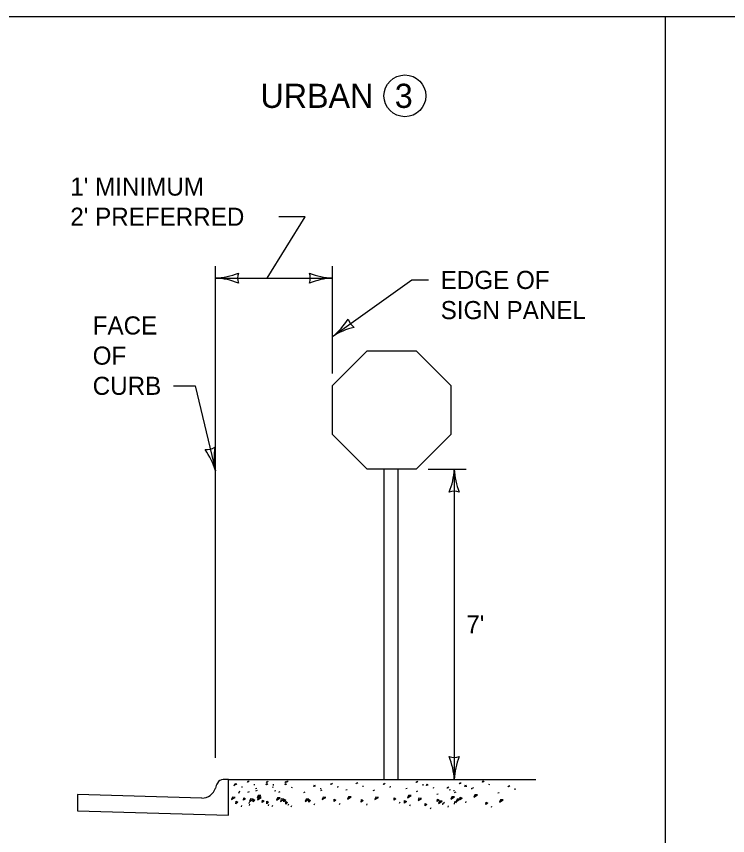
# Model space of a CAD drawing. Extents: x 49991.4 to 50021, y 49987.6 to 50011.4.
# Drawn here: x 50005.916 to 50008.274, y 49996.284 to 49998.999 of the extents above; entities that cross this region are included whole.
import ezdxf

# ---------------------------------------------------------------- set-up
doc = ezdxf.new("R2010")
doc.units = 0
for name, color, linetype in [('Level 1', 7, 'Continuous'), ('Level 2', 7, 'Continuous'), ('Level 3', 7, 'Continuous')]:
    doc.layers.add(name, color=color, linetype=linetype)

msp = doc.modelspace()

# ---------------------------------------------------------------- linework, layer by layer
at = {"layer": 'Level 1'}
for p, q in [((50007.1354, 49996.4699), (50007.1354, 49997.4987)), ((50007.1816, 49996.4699), (50007.1816, 49997.4987)), ((50006.6189, 49996.4699), (50006.6019, 49996.4699)), ((50006.6189, 49996.4699), (50007.6386, 49996.4699)), ((50006.6189, 49996.3514), (50006.6189, 49996.4699)), ((50006.6402, 49996.4554), (50006.637, 49996.4475)), ((50006.6411, 49996.4529), (50006.6431, 49996.4577)), ((50006.6456, 49996.454), (50006.6411, 49996.4529)), ((50006.6431, 49996.4577), (50006.6456, 49996.454)), ((50006.682, 49996.4609), (50006.684, 49996.4657)), ((50006.6865, 49996.462), (50006.682, 49996.4609)), ((50006.684, 49996.4657), (50006.6865, 49996.462)), ((50006.7049, 49996.4514), (50006.7054, 49996.455)), ((50006.7436, 49996.4529), (50006.7456, 49996.4577)), ((50006.7481, 49996.454), (50006.7436, 49996.4529)), ((50006.7449, 49996.46), (50006.7469, 49996.4648)), ((50006.7494, 49996.4611), (50006.7449, 49996.46)), ((50006.7456, 49996.4577), (50006.7481, 49996.454)), ((50006.7469, 49996.4648), (50006.7494, 49996.4611)), ((50006.7678, 49996.4505), (50006.7683, 49996.4541)), ((50006.8065, 49996.452), (50006.8085, 49996.4568)), ((50006.811, 49996.4531), (50006.8065, 49996.452)), ((50006.8074, 49996.46), (50006.8094, 49996.4648)), ((50006.8119, 49996.4611), (50006.8074, 49996.46)), ((50006.8085, 49996.4568), (50006.811, 49996.4531)), ((50006.8111, 49996.4609), (50006.8131, 49996.4657)), ((50006.8156, 49996.462), (50006.8111, 49996.4609)), ((50006.8131, 49996.4657), (50006.8156, 49996.462)), ((50006.9018, 49996.4473), (50006.9039, 49996.452)), ((50006.9039, 49996.452), (50006.9063, 49996.4484)), ((50006.9587, 49996.4537), (50006.9607, 49996.4585)), ((50006.9632, 49996.4548), (50006.9587, 49996.4537)), ((50006.9607, 49996.4585), (50006.9632, 49996.4548)), ((50007.0425, 49996.4553), (50007.0446, 49996.46)), ((50007.0446, 49996.46), (50007.047, 49996.4564)), ((50007.1326, 49996.4537), (50007.1347, 49996.4585)), ((50007.1371, 49996.4548), (50007.1326, 49996.4537)), ((50007.1347, 49996.4585), (50007.1371, 49996.4548)), ((50007.2416, 49996.46), (50007.2437, 49996.4648)), ((50007.2461, 49996.4611), (50007.2416, 49996.46)), ((50007.2437, 49996.4648), (50007.2461, 49996.4611)), ((50007.2646, 49996.4505), (50007.265, 49996.4541)), ((50007.276, 49996.4505), (50007.278, 49996.4552)), ((50007.2805, 49996.4515), (50007.276, 49996.4505)), ((50007.278, 49996.4552), (50007.2805, 49996.4515)), ((50007.385, 49996.4553), (50007.3871, 49996.46)), ((50007.3895, 49996.4564), (50007.385, 49996.4553)), ((50007.3871, 49996.46), (50007.3895, 49996.4564)), ((50007.4024, 49996.4473), (50007.4044, 49996.452)), ((50007.4044, 49996.452), (50007.4068, 49996.4484)), ((50007.4608, 49996.4616), (50007.4629, 49996.4663)), ((50007.4653, 49996.4627), (50007.4608, 49996.4616)), ((50007.4629, 49996.4663), (50007.4653, 49996.4627)), ((50007.4837, 49996.452), (50007.4842, 49996.4557)), ((50007.5462, 49996.4457), (50007.5483, 49996.4505)), ((50007.5483, 49996.4505), (50007.5507, 49996.4468)), ((50006.6551, 49996.4314), (50006.6519, 49996.4235)), ((50006.664, 49996.4433), (50006.6645, 49996.447)), ((50006.6871, 49996.4287), (50006.6824, 49996.4271)), ((50006.7128, 49996.4405), (50006.7082, 49996.4389)), ((50006.7136, 49996.4334), (50006.709, 49996.4318)), ((50006.7665, 49996.4433), (50006.767, 49996.447)), ((50006.7765, 49996.4325), (50006.7719, 49996.4309)), ((50006.7896, 49996.4287), (50006.7849, 49996.4271)), ((50006.8294, 49996.4424), (50006.8299, 49996.4461)), ((50006.8719, 49996.4278), (50006.8672, 49996.4262)), ((50006.9063, 49996.4484), (50006.9018, 49996.4473)), ((50006.9287, 49996.4342), (50006.9241, 49996.4326)), ((50006.9247, 49996.4377), (50006.9252, 49996.4414)), ((50006.9816, 49996.4441), (50006.9821, 49996.4478)), ((50007.0125, 49996.4358), (50007.0079, 49996.4342)), ((50007.0654, 49996.4457), (50007.0659, 49996.4494)), ((50007.1026, 49996.4342), (50007.098, 49996.4326)), ((50007.1555, 49996.4441), (50007.156, 49996.4478)), ((50007.2117, 49996.4405), (50007.2071, 49996.4389)), ((50007.246, 49996.4309), (50007.2414, 49996.4293)), ((50007.2989, 49996.4409), (50007.2994, 49996.4445)), ((50007.3444, 49996.441), (50007.3464, 49996.4457)), ((50007.3488, 49996.4421), (50007.3444, 49996.441)), ((50007.3464, 49996.4457), (50007.3488, 49996.4421)), ((50007.3551, 49996.4358), (50007.3504, 49996.4342)), ((50007.3673, 49996.4314), (50007.3678, 49996.435)), ((50007.3724, 49996.4278), (50007.3678, 49996.4262)), ((50007.4068, 49996.4484), (50007.4024, 49996.4473)), ((50007.4079, 49996.4457), (50007.4084, 49996.4494)), ((50007.4253, 49996.4377), (50007.4258, 49996.4414)), ((50007.4309, 49996.4421), (50007.4262, 49996.4405)), ((50007.5162, 49996.4262), (50007.5116, 49996.4246)), ((50007.5507, 49996.4468), (50007.5462, 49996.4457)), ((50007.5691, 49996.4361), (50007.5696, 49996.4398)), ((50006.5306, 49996.4081), (50006.1189, 49996.4205)), ((50006.1189, 49996.4205), (50006.1189, 49996.3665)), ((50006.6319, 49996.4112), (50006.6287, 49996.4033)), ((50006.6287, 49996.4033), (50006.6408, 49996.4109)), ((50006.6408, 49996.4109), (50006.6319, 49996.4112)), ((50006.6434, 49996.3897), (50006.6439, 49996.398)), ((50006.6439, 49996.398), (50006.6497, 49996.3947)), ((50006.6692, 49996.4016), (50006.6696, 49996.4098)), ((50006.6755, 49996.4065), (50006.6692, 49996.4016)), ((50006.6696, 49996.4098), (50006.6755, 49996.4065)), ((50006.6917, 49996.4056), (50006.6884, 49996.3977)), ((50006.6884, 49996.3977), (50006.7005, 49996.4054)), ((50006.7005, 49996.4054), (50006.6917, 49996.4056)), ((50006.7003, 49996.3962), (50006.7008, 49996.4044)), ((50006.7066, 49996.4011), (50006.7003, 49996.3962)), ((50006.7008, 49996.4044), (50006.7066, 49996.4011)), ((50006.7174, 49996.4175), (50006.7142, 49996.4096)), ((50006.7142, 49996.4096), (50006.7263, 49996.4172)), ((50006.7182, 49996.4104), (50006.715, 49996.4025)), ((50006.715, 49996.4025), (50006.7271, 49996.4101)), ((50006.7263, 49996.4172), (50006.7174, 49996.4175)), ((50006.7271, 49996.4101), (50006.7182, 49996.4104)), ((50006.7308, 49996.3936), (50006.7313, 49996.4018)), ((50006.7371, 49996.3985), (50006.7308, 49996.3936)), ((50006.7313, 49996.4018), (50006.7371, 49996.3985)), ((50006.7459, 49996.3897), (50006.7464, 49996.398)), ((50006.7464, 49996.398), (50006.7522, 49996.3947)), ((50006.7811, 49996.4095), (50006.7779, 49996.4016)), ((50006.7779, 49996.4016), (50006.79, 49996.4092)), ((50006.79, 49996.4092), (50006.7811, 49996.4095)), ((50006.7942, 49996.4056), (50006.7909, 49996.3977)), ((50006.7909, 49996.3977), (50006.803, 49996.4054)), ((50006.803, 49996.4054), (50006.7942, 49996.4056)), ((50006.8028, 49996.3962), (50006.8033, 49996.4044)), ((50006.8091, 49996.4011), (50006.8028, 49996.3962)), ((50006.8033, 49996.4044), (50006.8091, 49996.4011)), ((50006.8088, 49996.3888), (50006.8093, 49996.3971)), ((50006.8093, 49996.3971), (50006.8151, 49996.3938)), ((50006.8765, 49996.4047), (50006.8732, 49996.3968)), ((50006.8732, 49996.3968), (50006.8853, 49996.4045)), ((50006.8853, 49996.4045), (50006.8765, 49996.4047)), ((50006.8851, 49996.3953), (50006.8856, 49996.4035)), ((50006.8914, 49996.4002), (50006.8851, 49996.3953)), ((50006.8856, 49996.4035), (50006.8914, 49996.4002)), ((50006.9333, 49996.4112), (50006.9301, 49996.4033)), ((50006.9301, 49996.4033), (50006.9422, 49996.4109)), ((50006.9422, 49996.4109), (50006.9333, 49996.4112)), ((50006.9689, 49996.3968), (50006.9694, 49996.4051)), ((50006.9752, 49996.4018), (50006.9689, 49996.3968)), ((50006.9694, 49996.4051), (50006.9752, 49996.4018)), ((50007.0171, 49996.4127), (50007.0139, 49996.4048)), ((50007.0139, 49996.4048), (50007.026, 49996.4125)), ((50007.026, 49996.4125), (50007.0171, 49996.4127)), ((50007.059, 49996.3953), (50007.0595, 49996.4035)), ((50007.0653, 49996.4002), (50007.059, 49996.3953)), ((50007.0595, 49996.4035), (50007.0653, 49996.4002)), ((50007.1073, 49996.4112), (50007.104, 49996.4033)), ((50007.104, 49996.4033), (50007.1161, 49996.4109)), ((50007.1161, 49996.4109), (50007.1073, 49996.4112)), ((50007.168, 49996.4016), (50007.1685, 49996.4098)), ((50007.1743, 49996.4065), (50007.168, 49996.4016)), ((50007.1685, 49996.4098), (50007.1743, 49996.4065)), ((50007.2024, 49996.392), (50007.2028, 49996.4002)), ((50007.2087, 49996.397), (50007.2024, 49996.392)), ((50007.2028, 49996.4002), (50007.2087, 49996.397)), ((50007.2163, 49996.4175), (50007.213, 49996.4096)), ((50007.213, 49996.4096), (50007.2251, 49996.4172)), ((50007.2251, 49996.4172), (50007.2163, 49996.4175)), ((50007.2506, 49996.4079), (50007.2474, 49996.4)), ((50007.2474, 49996.4), (50007.2595, 49996.4076)), ((50007.2595, 49996.4076), (50007.2506, 49996.4079)), ((50007.3144, 49996.4215), (50007.3098, 49996.4199)), ((50007.3114, 49996.3968), (50007.3119, 49996.4051)), ((50007.3177, 49996.4018), (50007.3114, 49996.3968)), ((50007.3119, 49996.4051), (50007.3177, 49996.4018)), ((50007.319, 49996.3984), (50007.3157, 49996.3905)), ((50007.3157, 49996.3905), (50007.3279, 49996.3982)), ((50007.3279, 49996.3982), (50007.319, 49996.3984)), ((50007.3597, 49996.4127), (50007.3564, 49996.4048)), ((50007.3564, 49996.4048), (50007.3685, 49996.4125)), ((50007.3685, 49996.4125), (50007.3597, 49996.4127)), ((50007.3687, 49996.3888), (50007.3692, 49996.3971)), ((50007.3692, 49996.3971), (50007.375, 49996.3938)), ((50007.377, 49996.4047), (50007.3737, 49996.3968)), ((50007.3737, 49996.3968), (50007.3859, 49996.4045)), ((50007.3859, 49996.4045), (50007.377, 49996.4047)), ((50007.3872, 49996.4032), (50007.3877, 49996.4114)), ((50007.3935, 49996.4081), (50007.3872, 49996.4032)), ((50007.3877, 49996.4114), (50007.3935, 49996.4081)), ((50007.406, 49996.397), (50007.4044, 49996.3927)), ((50007.4355, 49996.419), (50007.4322, 49996.4112)), ((50007.4322, 49996.4112), (50007.4443, 49996.4188)), ((50007.4443, 49996.4188), (50007.4355, 49996.419)), ((50007.5208, 49996.4032), (50007.5176, 49996.3953)), ((50007.5176, 49996.3953), (50007.5297, 49996.4029)), ((50007.5297, 49996.4029), (50007.5208, 49996.4032)), ((50006.6497, 49996.3947), (50006.6434, 49996.3897)), ((50006.6622, 49996.3836), (50006.6606, 49996.3793)), ((50006.688, 49996.3954), (50006.6864, 49996.3911)), ((50006.6888, 49996.3883), (50006.6872, 49996.384)), ((50006.7522, 49996.3947), (50006.7459, 49996.3897)), ((50006.7517, 49996.3874), (50006.7501, 49996.3831)), ((50006.7647, 49996.3836), (50006.7631, 49996.3793)), ((50006.8151, 49996.3938), (50006.8088, 49996.3888)), ((50006.8179, 49996.3883), (50006.8163, 49996.384)), ((50006.8276, 49996.3827), (50006.826, 49996.3784)), ((50006.9039, 49996.3891), (50006.9023, 49996.3848)), ((50006.9877, 49996.3907), (50006.9861, 49996.3864)), ((50007.0778, 49996.3891), (50007.0762, 49996.3848)), ((50007.1868, 49996.3954), (50007.1852, 49996.3911)), ((50007.2212, 49996.3858), (50007.2196, 49996.3816)), ((50007.2707, 49996.3825), (50007.2712, 49996.3908)), ((50007.277, 49996.3875), (50007.2707, 49996.3825)), ((50007.2712, 49996.3908), (50007.277, 49996.3875)), ((50007.2895, 49996.3763), (50007.288, 49996.3721)), ((50007.3302, 49996.3907), (50007.3286, 49996.3864)), ((50007.335, 49996.3938), (50007.3287, 49996.3888)), ((50007.3475, 49996.3827), (50007.346, 49996.3784)), ((50007.4726, 49996.3873), (50007.4731, 49996.3955)), ((50007.4789, 49996.3922), (50007.4726, 49996.3873)), ((50007.4731, 49996.3955), (50007.4789, 49996.3922)), ((50007.4914, 49996.3811), (50007.4898, 49996.3768)), ((50006.1189, 49996.3665), (50006.6189, 49996.3514))]:
    msp.add_line(p, q, dxfattribs=at)
for points in [[(49999.3835, 49998.9992), (50016.7501, 49998.9992), (50016.7501, 49987.7988), (49999.3835, 49987.7988)], [(50007.0783, 49997.8908), (50007.2411, 49997.8908), (50007.3558, 49997.7761), (50007.3558, 49997.6134), (50007.2411, 49997.4987), (50007.0783, 49997.4987), (50006.9637, 49997.6134), (50006.9637, 49997.7761)]]:
    msp.add_lwpolyline(points, close=True, dxfattribs=at)
for centre, radius, start, end in [((50006.6266, 49996.4306), 0.0521, 148.1841, 167.8949), ((50006.6002, 49996.4505), 0.0194, 85.2356, 156.6889), ((50006.5301, 49996.4559), 0.0477, 270.5454, 342.4535)]:
    msp.add_arc(centre, radius, start, end, dxfattribs=at)
at = {"layer": 'Level 2'}
msp.add_circle((50007.2039, 49998.7359), 0.0693, dxfattribs=at)
at = {"layer": 'Level 3'}
for p, q in [((50008.0668, 49998.9992), (50008.0668, 49994.0732)), ((50006.7471, 49998.1319), (50006.8735, 49998.3352)), ((50006.8735, 49998.3352), (50006.786, 49998.3352)), ((50006.5756, 49996.5415), (50006.5756, 49998.1719)), ((50006.9636, 49997.8161), (50006.9636, 49998.1719)), ((50006.5756, 49998.1319), (50006.9636, 49998.1319)), ((50006.9636, 49997.9381), (50007.2272, 49998.1258)), ((50007.2272, 49998.1258), (50007.2826, 49998.1258)), ((50006.4368, 49997.7749), (50006.5088, 49997.7749)), ((50006.5088, 49997.7749), (50006.5756, 49997.4934)), ((50007.2811, 49997.4987), (50007.4075, 49997.4987)), ((50007.3675, 49997.4987), (50007.3675, 49996.4699))]:
    msp.add_line(p, q, dxfattribs=at)
for centre, radius, start, end in [((50006.5641, 49998.3646), 0.233, 272.8273, 292.0772), ((50006.7039, 49998.1319), 0.0548, 162.1388, 197.8612), ((50006.9728, 49998.354), 0.2223, 247.456, 267.6395), ((50006.8354, 49998.1319), 0.0548, 342.1388, 17.8612), ((50006.5665, 49997.9097), 0.2223, 67.456, 87.6395), ((50006.9751, 49997.8992), 0.233, 92.8273, 112.0772), ((50006.8193, 49998.121), 0.233, 308.2806, 327.5305), ((50007.068, 49998.0125), 0.0548, 197.5921, 233.3145), ((50007.085, 49997.7518), 0.2223, 102.9093, 123.0928), ((50006.5452, 49997.618), 0.0548, 265.8498, 301.5721), ((50006.3523, 49997.4271), 0.233, 16.5382, 35.7881), ((50006.7936, 49997.5372), 0.2223, 171.1669, 191.3505), ((50007.1454, 49997.5079), 0.2223, 337.456, 357.6395), ((50007.6002, 49997.5102), 0.233, 182.8273, 202.0772), ((50007.3675, 49997.3705), 0.0548, 72.1388, 107.8612), ((50007.3675, 49996.5981), 0.0548, 252.1388, 287.8612), ((50007.1348, 49996.4584), 0.233, 2.8273, 22.0772), ((50007.5896, 49996.4607), 0.2223, 157.456, 177.6395)]:
    msp.add_arc(centre, radius, start, end, dxfattribs=at)

# ---------------------------------------------------------------- texts
at = {"layer": 'Level 2'}
for s, height, p in [('URBAN', 0.08, (50006.7249, 49998.6959)), ('3', 0.08, (50007.1703, 49998.6959)), ("1' MINIMUM", 0.06, (50006.0945, 49998.4052)), ("2' PREFERRED", 0.06, (50006.0945, 49998.3052)), ('EDGE OF', 0.06, (50007.3226, 49998.0958)), ('SIGN PANEL', 0.06, (50007.3226, 49997.9958)), ('FACE', 0.06, (50006.1687, 49997.9449)), ('OF', 0.06, (50006.1687, 49997.8449)), ('CURB', 0.06, (50006.1687, 49997.7449)), ("7'", 0.06, (50007.4075, 49996.9543))]:
    msp.add_text(s, height=height, dxfattribs=at).set_placement(p)

doc.saveas('drawing.dxf')
